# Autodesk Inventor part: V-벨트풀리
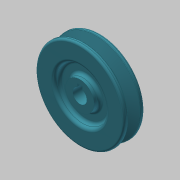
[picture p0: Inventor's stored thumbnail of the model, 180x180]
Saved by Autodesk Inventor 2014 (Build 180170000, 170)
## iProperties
Created: 2019-09
Part Number: V-벨트풀리
Material: 알루미늄 6061
Document SubType Name: Modeling
Designer: mduedu
Density: 1 g/cm^3
Appearance: Cadet Blue
Author: mduedu
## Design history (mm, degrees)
sketch "스케치1"
  geometry: L1 (-10, 0)-(10, 0); L2 (10, 0)-(10, 43.5); L3 (10, 43.5)-(-10, 43.5); L4 (-10, 43.5)-(-10, 0); L5 (0, 0)-(0, 43.5); L6 (-5.976, 43.5)-(-2.154, 31); L7 (-2.154, 31)-(2.154, 31); L8 (2.154, 31)-(5.976, 43.5); L9 (-10, 39)-(10, 39); 3 further points
  constraints: 18 end point, 8 point on line, 3 perpendicular, 2 midpoint, 2 parallel, 1 coincident, 1 horizontal, 1 other
  dimensions: "d0" = 87 diameter of L3 L1; "d3" = 12.5 distance between parallel lines of L7 L3; "d4" = 34 deg angle of L8 L6; "d5" = 20 distance between parallel lines of L2 L4; "d6" = 8 distance between parallel lines of L9 L7; "d7" = 9.2 distance of point (4.6, 39) point (-4.6, 39)
revolve "회전1" sketch "스케치1" stored, may be unused: angle "d8" = 90 deg
sketch "스케치2"
  geometry: C1 r 14 at (0, 0); C2 r 25 at (0, 0); 1 further point
  constraints: 2 centre point, 2 coincident
  dimensions: "d9" = 28 diameter of C1; "d10" = 50 diameter of C2
extrude "돌출1" cut sketch "스케치2" distance "d11" = 6; taper "d12" = 0 deg
fillet "모깎기1" dims "d13" = 3
fillet "모깎기2" dims "d14" = 3
fillet "모깎기3" dims "d15" = 0.5, "d16" = 1, "d17" = 2
sketch "스케치3"
  geometry: L1 (-2.5, 6.538)-(2.5, 6.538); L2 (2.5, 6.538)-(2.5, 9.3); L3 (2.5, 9.3)-(-2.5, 9.3); L4 (-2.5, 9.3)-(-2.5, 6.538); A1 r 7 centre (0, 0) between (-2.5, 6.538) and (2.5, 6.538); 1 further point
  constraints: 8 end point, 2 parallel, 2 point on circle, 1 centre point, 1 coincident, 1 horizontal, 1 perpendicular
  dimensions: "d18" = 14 diameter of A1; "d20" = 5 distance of L2.end L3.end; "d21" = 16.3 dimension on A1 L3
extrude "돌출2" cut sketch "스케치3" stored distance "d22" = 6; taper "d23" = 0 deg
node "솔리드1"
mirror "대칭1"
